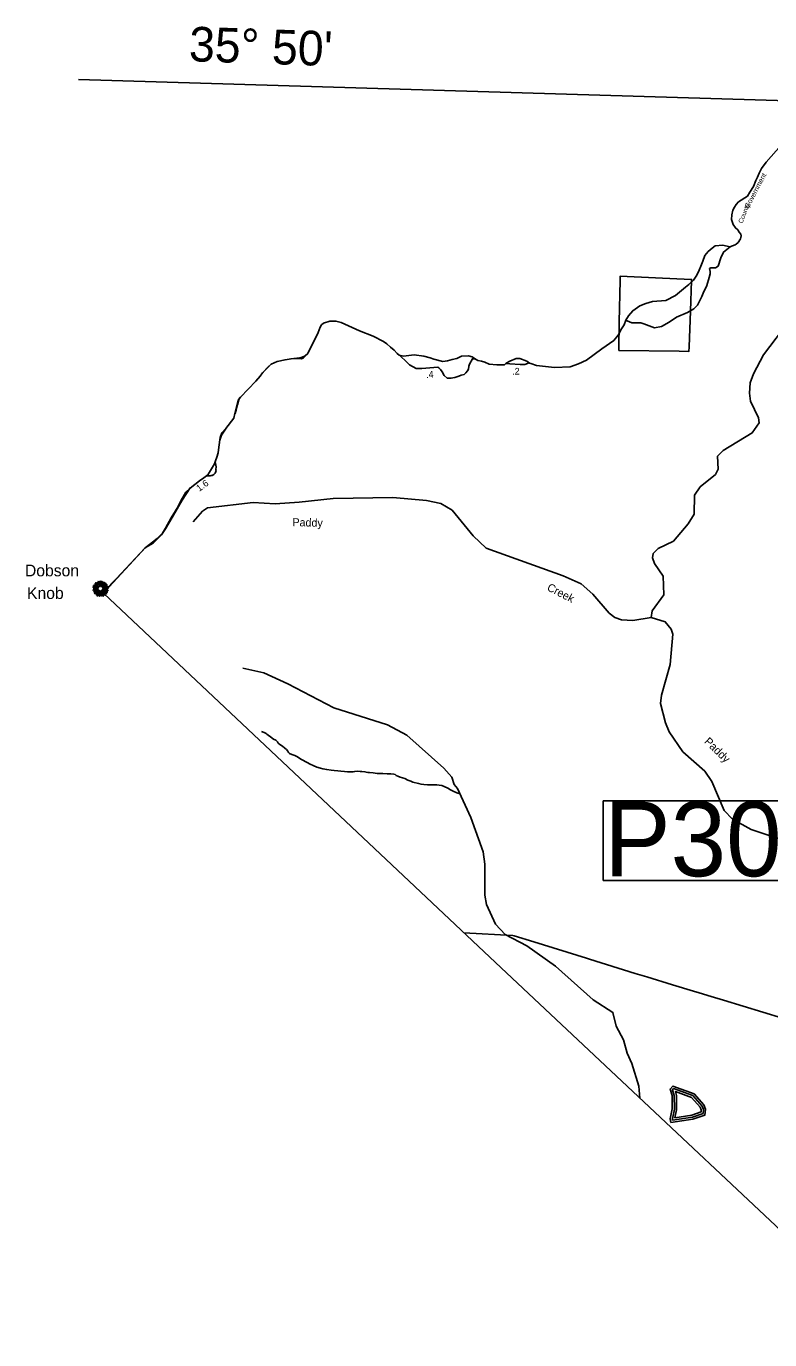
# Model space of a CAD drawing. Extents: x 1113032 to 1302912, y 664689 to 832535.
# Drawn here: x 1113032 to 1126972, y 747949 to 772573 of the extents above; entities that cross this region are included whole.
import ezdxf

# ---------------------------------------------------------------- set-up
doc = ezdxf.new("R2010")
doc.units = 0
for name, color, linetype in [('Exist Boundary Land Use Forest National US Forest Service', 7, 'Continuous'), ('Exist Boundary Political CountyLine', 7, 'Continuous'), ('Exist Boundary Political CountyLine Road Label', 7, 'Continuous'), ('Exist Geographical Mountain Summit CELL', 7, 'Continuous'), ('Exist Geographical Mountain Summit Label', 7, 'Continuous'), ('Exist Hydrographic Buffer Line', 7, 'Continuous'), ('Exist Hydrographic Creek Single Shore', 7, 'Continuous'), ('Exist Hydrographic Creek Single Shore Label', 7, 'Continuous'), ('Exist Hydrographic Lake Shore', 7, 'Continuous'), ('Exist Hydrographic Misc Water Feature', 7, 'Continuous'), ('Exist Road Non-System Type 51', 7, 'Continuous'), ('Exist Road Primary NC Structure Pipe Number Label', 7, 'Continuous'), ('Exist Road Secondary Mileage Hundredths English Label', 7, 'Continuous'), ('Exist Road Secondary Type 51 Label', 7, 'Continuous'), ('Exist Road State Agency Type 20 National Forest', 7, 'Continuous'), ('Map Preparation Longitude Latitude Label', 7, 'Continuous'), ('Map Preparation Longitude Latitude Lines', 7, 'Continuous')]:
    doc.layers.add(name, color=color, linetype=linetype)

msp = doc.modelspace()

# ---------------------------------------------------------------- linework, layer by layer
at = {"layer": 'Exist Boundary Land Use Forest National US Forest Service'}
for points in [[(1124141, 766495), (1125276, 766481), (1125457, 766479), (1125460, 766561), (1125485, 767231), (1125506, 767805), (1125507, 767828), (1125497, 767828), (1124832, 767859), (1124170, 767889), (1124168, 767806), (1124152, 767031), (1124149, 766860), (1124145, 766703), (1124141, 766495)], [(1127583, 753864), (1126104, 754314), (1125872, 754385), (1125646, 754454), (1125544, 754485), (1125152, 754604), (1124668, 754752), (1124450, 754818), (1123591, 755084), (1123537, 755101), (1122546, 755407), (1122181, 755520), (1122154, 755528), (1121238, 755578)]]:
    msp.add_lwpolyline(points, dxfattribs=at)
at = {"layer": 'Exist Boundary Political CountyLine'}
for points in [[(1127280, 770451), (1126903, 770025), (1126819, 769908), (1126773, 769821), (1126744, 769744), (1126712, 769679), (1126669, 769568), (1126598, 769462), (1126555, 769385), (1126384, 769280), (1126341, 769230), (1126310, 769182), (1126280, 769127), (1126261, 769039), (1126255, 768950), (1126284, 768855), (1126328, 768794), (1126373, 768758), (1126400, 768715), (1126433, 768676), (1126438, 768644), (1126431, 768616), (1126422, 768589), (1126380, 768518), (1126345, 768487), (1126323, 768473)], [(1126323, 768473), (1126227, 768438), (1126090, 768470), (1125952, 768458), (1125894, 768416), (1125817, 768348), (1125758, 768274), (1125715, 768169), (1125682, 768076), (1125646, 768001), (1125607, 767904), (1125545, 767816), (1125456, 767729), (1125393, 767682), (1125204, 767526), (1125023, 767435), (1124774, 767412), (1124651, 767374), (1124536, 767331), (1124403, 767241), (1124324, 767142), (1124277, 767063), (1124245, 766978), (1124193, 766901), (1124133, 766781), (1124050, 766683), (1123821, 766524), (1123537, 766316), (1123385, 766247), (1123231, 766191), (1122936, 766174), (1122597, 766214), (1122490, 766252)], [(1122490, 766252), (1122469, 766260), (1122419, 766297), (1122285, 766345), (1122215, 766345), (1122099, 766297), (1122030, 766259), (1121999, 766228), (1121857, 766226), (1121714, 766240), (1121630, 766276), (1121569, 766296), (1121500, 766306), (1121468, 766323), (1121395, 766376), (1121322, 766394), (1121191, 766386), (1121106, 766342), (1121015, 766325), (1120927, 766299), (1120840, 766288), (1120671, 766333), (1120608, 766357), (1120485, 766388), (1120308, 766412), (1120105, 766390), (1120025, 766406), (1119986, 766437), (1119932, 766499), (1119863, 766555), (1119793, 766619), (1119729, 766661), (1119537, 766761), (1119280, 766862), (1119008, 766989), (1118935, 767017), (1118839, 767045), (1118723, 767045), (1118608, 767008), (1118565, 766975), (1118544, 766934), (1118505, 766829), (1118311, 766437), (1118264, 766394), (1118207, 766370), (1118154, 766355), (1117998, 766340), (1117885, 766321), (1117736, 766286), (1117621, 766237), (1117567, 766189), (1117462, 766076), (1117416, 766011), (1117339, 765919), (1117050, 765619), (1117002, 765561), (1116945, 765312), (1116924, 765229), (1116772, 765031), (1116696, 764953), (1116666, 764866), (1116640, 764683), (1116629, 764579), (1116606, 764492), (1116580, 764424), (1116563, 764369), (1116470, 764214), (1116433, 764162), (1116363, 764107), (1116281, 764053), (1116191, 763980), (1116103, 763916), (1116025, 763836), (1115928, 763677), (1115878, 763571), (1115746, 763360), (1115643, 763163), (1115584, 763073), (1115485, 762972), (1115253, 762790), (1114726, 762220), (1114501, 761992), (1114483, 761941)], [(1114483, 761941), (1121830, 755021), (1129762, 747575), (1131999, 745470), (1132534, 744970), (1136601, 740851), (1137713, 739712), (1140850, 736413), (1141222, 736061), (1141222, 736061), (1142712, 734629), (1146817, 730670), (1148405, 729150)]]:
    msp.add_lwpolyline(points, dxfattribs=at)
at = {"layer": 'Exist Geographical Mountain Summit CELL'}
for points in [[(1114312, 762114), (1114351, 762084), (1114354, 762086), (1114316, 762119)], [(1114332, 762139), (1114368, 762102), (1114371, 762104), (1114336, 762144)], [(1114340, 762112), (1114373, 762082), (1114375, 762085), (1114343, 762117)], [(1114360, 762141), (1114375, 762119), (1114377, 762120), (1114364, 762145)], [(1114371, 762162), (1114397, 762096), (1114400, 762097), (1114376, 762165)], [(1114405, 762110), (1114407, 762111), (1114398, 762159), (1114394, 762158)], [(1114409, 762172), (1114413, 762120), (1114417, 762120), (1114415, 762173)], [(1114425, 762118), (1114429, 762118), (1114433, 762165), (1114427, 762165)], [(1114437, 762089), (1114452, 762166), (1114447, 762168), (1114434, 762090)], [(1114440, 762068), (1114443, 762066), (1114492, 762150), (1114487, 762154)], [(1114455, 762125), (1114458, 762123), (1114468, 762150), (1114463, 762152)], [(1114462, 762069), (1114464, 762067), (1114519, 762131), (1114515, 762136)], [(1114499, 762141), (1114478, 762107), (1114481, 762106), (1114503, 762137)], [(1114519, 762097), (1114521, 762094), (1114544, 762111), (1114540, 762114)], [(1114282, 762007), (1114283, 762001), (1114320, 762012), (1114317, 762015)], [(1114283, 762044), (1114355, 762037), (1114356, 762040), (1114283, 762049)], [(1114286, 762065), (1114327, 762056), (1114329, 762059), (1114287, 762070)], [(1114289, 762085), (1114311, 762076), (1114313, 762079), (1114290, 762090)], [(1114292, 761979), (1114294, 761974), (1114340, 761994), (1114338, 761999)], [(1114296, 762027), (1114325, 762028), (1114325, 762032), (1114294, 762032)], [(1114303, 761942), (1114306, 761938), (1114334, 761959), (1114332, 761963)], [(1114309, 761963), (1114338, 761980), (1114336, 761983), (1114307, 761968)], [(1114311, 762096), (1114337, 762079), (1114339, 762082), (1114314, 762100)], [(1114327, 762068), (1114358, 762056), (1114359, 762058), (1114330, 762072)], [(1114328, 762018), (1114329, 762013), (1114362, 762021), (1114361, 762025)], [(1114334, 761923), (1114337, 761920), (1114378, 761968), (1114375, 761970)], [(1114349, 761954), (1114369, 761972), (1114365, 761974), (1114345, 761957)], [(1114346, 761972), (1114349, 761969), (1114383, 761997), (1114381, 762000)], [(1114374, 761954), (1114349, 761915), (1114352, 761912), (1114378, 761952)], [(1114355, 762004), (1114358, 761999), (1114386, 762014), (1114385, 762017)], [(1114359, 761895), (1114364, 761892), (1114375, 761917), (1114371, 761919)], [(1114364, 762073), (1114389, 762054), (1114391, 762057), (1114366, 762076)], [(1114364, 762043), (1114381, 762041), (1114382, 762043), (1114365, 762048)], [(1114377, 761932), (1114382, 761931), (1114408, 761989), (1114406, 761990)], [(1114383, 762086), (1114397, 762070), (1114399, 762072), (1114387, 762089)], [(1114384, 761982), (1114387, 761979), (1114398, 761995), (1114396, 761997)], [(1114389, 761897), (1114401, 761940), (1114397, 761940), (1114385, 761898)], [(1114399, 761887), (1114403, 761886), (1114416, 761975), (1114413, 761976)], [(1114415, 762098), (1114416, 762069), (1114419, 762070), (1114419, 762099)], [(1114424, 761991), (1114428, 761954), (1114433, 761954), (1114427, 761992)], [(1114430, 761932), (1114434, 761890), (1114438, 761891), (1114435, 761932)], [(1114440, 761982), (1114449, 761952), (1114453, 761954), (1114442, 761983)], [(1114450, 761916), (1114445, 761946), (1114441, 761946), (1114446, 761915)], [(1114449, 762003), (1114487, 761967), (1114490, 761972), (1114450, 762005)], [(1114455, 761980), (1114505, 761905), (1114509, 761908), (1114457, 761981)], [(1114455, 761937), (1114472, 761887), (1114476, 761889), (1114458, 761938)], [(1114458, 762049), (1114460, 762047), (1114509, 762082), (1114506, 762087)], [(1114460, 762020), (1114520, 762008), (1114522, 762012), (1114461, 762023)], [(1114465, 761943), (1114481, 761913), (1114485, 761916), (1114469, 761944)], [(1114474, 762033), (1114474, 762031), (1114504, 762031), (1114505, 762036)], [(1114474, 762000), (1114552, 761962), (1114554, 761967), (1114475, 762003)], [(1114475, 762046), (1114476, 762044), (1114555, 762073), (1114553, 762077)], [(1114487, 761954), (1114517, 761925), (1114520, 761928), (1114489, 761957)], [(1114504, 761955), (1114534, 761929), (1114537, 761933), (1114506, 761957)], [(1114513, 761966), (1114538, 761953), (1114540, 761956), (1114515, 761970)], [(1114519, 762074), (1114547, 762089), (1114544, 762094), (1114518, 762077)], [(1114518, 762032), (1114570, 762036), (1114570, 762040), (1114518, 762036)], [(1114521, 762046), (1114558, 762053), (1114556, 762058), (1114520, 762048)], [(1114527, 761990), (1114548, 761982), (1114550, 761986), (1114528, 761993)], [(1114532, 762020), (1114559, 762018), (1114559, 762022), (1114533, 762024)], [(1114536, 762003), (1114565, 761996), (1114565, 762001), (1114537, 762008)]]:
    msp.add_lwpolyline(points, close=True, dxfattribs=at)
at = {"layer": 'Exist Hydrographic Buffer Line'}
for points in [[(1125151, 752065), (1125146, 752089), (1125184, 752270), (1125183, 752528), (1125151, 752637), (1125169, 752658), (1125530, 752525), (1125705, 752331), (1125730, 752264), (1125721, 752191), (1125522, 752123), (1125151, 752065)], [(1125192, 752112), (1125223, 752262), (1125223, 752528), (1125220, 752552), (1125204, 752602), (1125507, 752491), (1125670, 752310), (1125689, 752259), (1125685, 752221), (1125512, 752162), (1125192, 752112)]]:
    msp.add_lwpolyline(points, dxfattribs=at)
at = {"layer": 'Exist Hydrographic Creek Single Shore'}
for points in [[(1124750, 761487), (1124770, 761611), (1124988, 761915), (1124973, 762267), (1124813, 762503), (1124774, 762606), (1124785, 762687), (1124880, 762784), (1125167, 762919), (1125444, 763245), (1125557, 763424), (1125560, 763781), (1125665, 763937), (1125955, 764171), (1126008, 764268), (1125990, 764511), (1126102, 764617), (1126645, 764951), (1126776, 765139), (1126762, 765231), (1126613, 765546), (1126592, 765694), (1126606, 765887), (1126670, 766060), (1126855, 766414), (1127350, 767064)], [(1124750, 761487), (1124406, 761431), (1124190, 761445), (1124066, 761491), (1123960, 761572), (1123654, 761929), (1123434, 762120), (1123097, 762272), (1121653, 762789), (1121409, 763021), (1121015, 763501), (1120802, 763624), (1120537, 763682), (1119905, 763740), (1118787, 763717), (1118151, 763651), (1117700, 763623), (1117284, 763645), (1116430, 763544), (1116337, 763480), (1116164, 763283)], [(1127344, 757276), (1126625, 757514), (1126272, 757708), (1126119, 757872), (1125885, 758412), (1125757, 758608), (1125342, 758971), (1125087, 759343), (1125017, 759512), (1124927, 759875), (1124940, 760032), (1125107, 760610), (1125158, 761177), (1125127, 761269), (1125014, 761406), (1124750, 761487)], [(1124537, 752481), (1124515, 752705), (1124386, 753127), (1124300, 753320), (1124232, 753574), (1124090, 753826), (1124031, 754086), (1123662, 754324), (1122955, 754955), (1122416, 755336), (1122014, 755548), (1121828, 755739), (1121664, 756110), (1121627, 756284), (1121628, 756862), (1121601, 757096), (1121370, 757737), (1121119, 758284), (1121055, 758360), (1121009, 758496), (1120864, 758666), (1120165, 759281), (1119804, 759475), (1118796, 759797), (1117934, 760248), (1117489, 760450), (1117092, 760540)]]:
    msp.add_lwpolyline(points, dxfattribs=at)
at = {"layer": 'Exist Hydrographic Lake Shore'}
msp.add_lwpolyline([(1125120, 752020), (1125105, 752089), (1125144, 752279), (1125143, 752528), (1125105, 752647), (1125157, 752705), (1125553, 752559), (1125739, 752352), (1125770, 752269), (1125758, 752161), (1125531, 752084), (1125120, 752020)], dxfattribs=at)
at = {"layer": 'Exist Hydrographic Misc Water Feature'}
msp.add_lwpolyline([(1121166, 758181), (1121106, 758201), (1121037, 758233), (1120987, 758260), (1120934, 758288), (1120867, 758318), (1120824, 758337), (1120772, 758346), (1120728, 758354), (1120698, 758355), (1120650, 758354), (1120630, 758353), (1120554, 758355), (1120488, 758361), (1120434, 758364), (1120388, 758380), (1120283, 758405), (1120242, 758422), (1120188, 758442), (1120127, 758468), (1120087, 758483), (1120042, 758498), (1119998, 758517), (1119965, 758530), (1119947, 758543), (1119921, 758554), (1119865, 758559), (1119797, 758561), (1119719, 758564), (1119612, 758567), (1119538, 758579), (1119470, 758581), (1119442, 758582), (1119406, 758589), (1119382, 758596), (1119326, 758601), (1119294, 758604), (1119248, 758608), (1119190, 758605), (1119164, 758598), (1119108, 758596), (1119056, 758597), (1118998, 758603), (1118928, 758611), (1118874, 758613), (1118803, 758621), (1118751, 758624), (1118665, 758637), (1118593, 758653), (1118550, 758664), (1118478, 758681), (1118413, 758714), (1118356, 758738), (1118298, 758768), (1118194, 758827), (1118145, 758858), (1118116, 758879), (1118066, 758899), (1118009, 758919), (1117967, 758938), (1117948, 758956), (1117939, 758983), (1117910, 759016), (1117880, 759042), (1117835, 759080), (1117788, 759109), (1117757, 759136), (1117740, 759161), (1117709, 759190), (1117667, 759211), (1117612, 759250), (1117569, 759282), (1117540, 759303), (1117528, 759315), (1117493, 759334), (1117443, 759350)], dxfattribs=at)
at = {"layer": 'Exist Road Non-System Type 51'}
msp.add_lwpolyline([(1116575, 764409), (1116593, 764312), (1116589, 764262), (1116591, 764242), (1116586, 764226), (1116572, 764196), (1116551, 764173), (1116518, 764154), (1116498, 764149), (1116480, 764145), (1116438, 764142), (1116414, 764148)], dxfattribs=at)
at = {"layer": 'Exist Road Primary NC Structure Pipe Number Label'}
msp.add_lwpolyline([(1123852, 758051), (1128850, 758051), (1128850, 756559), (1123852, 756559)], close=True, dxfattribs=at)
at = {"layer": 'Exist Road State Agency Type 20 National Forest'}
for points in [[(1124274, 767055), (1124301, 767052), (1124389, 767014), (1124505, 767012), (1124523, 767014), (1124556, 767012), (1124610, 766992), (1124811, 766919), (1124943, 766947), (1125084, 767028), (1125224, 767117), (1125429, 767206), (1125547, 767274), (1125616, 767343), (1125701, 767506), (1125727, 767570), (1125793, 767712), (1125836, 767865), (1125853, 767932), (1125854, 767974), (1125844, 768030), (1125867, 768047), (1125955, 768047), (1126004, 768076), (1126057, 768234), (1126106, 768339), (1126232, 768437)], [(1118054, 766345), (1118195, 766340), (1118231, 766357), (1118256, 766380), (1118266, 766392), (1118270, 766400)], [(1120030, 766405), (1120175, 766269), (1120220, 766226), (1120344, 766158), (1120451, 766160), (1120746, 766181), (1120770, 766169), (1120798, 766137), (1120831, 766094), (1120868, 766027), (1120926, 765975), (1120995, 765973), (1121065, 765990), (1121142, 766012), (1121187, 766030), (1121240, 766047), (1121274, 766077), (1121306, 766116), (1121321, 766145), (1121333, 766201)], [(1121333, 766201), (1121341, 766236), (1121396, 766341), (1121451, 766335)], [(1117451, 766060), (1117513, 766124), (1117590, 766209)], [(1122021, 766249), (1122096, 766247), (1122291, 766232), (1122381, 766233), (1122460, 766266)], [(1116946, 765315), (1116966, 765373), (1116992, 765478), (1117017, 765567), (1117032, 765598)], [(1116658, 764811), (1116695, 764906), (1116778, 765039)], [(1114510, 761985), (1115268, 762803), (1115412, 762882), (1115569, 763039), (1115641, 763150), (1115765, 763366), (1115955, 763686), (1116105, 763918)]]:
    msp.add_lwpolyline(points, dxfattribs=at)
at = {"layer": 'Map Preparation Longitude Latitude Lines'}
msp.add_line((1114014, 771573), (1128888, 771129), dxfattribs=at)

# ---------------------------------------------------------------- texts
at = {"layer": 'Exist Boundary Political CountyLine Road Label'}
msp.add_text('County', height=88.6, rotation=68.6702, dxfattribs=at).set_placement((1126460, 768869))
at = {"layer": 'Exist Geographical Mountain Summit Label'}
for s, p in [('Dobson', (1113007, 762261)), ('Knob', (1113046, 761837))]:
    msp.add_text(s, height=220, dxfattribs=at).set_placement(p)
at = {"layer": 'Exist Hydrographic Creek Single Shore Label'}
for s, rotation, p in [('Paddy', 358.6005, (1118021, 763202)), ('Creek', 332.8375, (1122783, 762006)), ('Paddy', 315.8031, (1125733, 759151))]:
    msp.add_text(s, height=150, rotation=rotation, dxfattribs=at).set_placement(p)
at = {"layer": 'Exist Road Primary NC Structure Pipe Number Label'}
msp.add_text('P300', height=1400, dxfattribs=at).set_placement((1123865, 756638))
at = {"layer": 'Exist Road Secondary Mileage Hundredths English Label'}
for s, rotation, p in [('.4', 3.9174, (1120533, 765978)), ('.2', 0.4661, (1122143, 766043)), ('1.6', 35.5791, (1116275, 763844))]:
    msp.add_text(s, height=125, rotation=rotation, dxfattribs=at).set_placement(p)
at = {"layer": 'Exist Road Secondary Type 51 Label'}
msp.add_text('Government', height=95, rotation=62.1467, dxfattribs=at).set_placement((1126577, 769151))
at = {"layer": 'Map Preparation Longitude Latitude Label'}
msp.add_text("35° 50'", height=650, rotation=357.9982, dxfattribs=at).set_placement((1116075, 771919))

doc.saveas('drawing.dxf')
